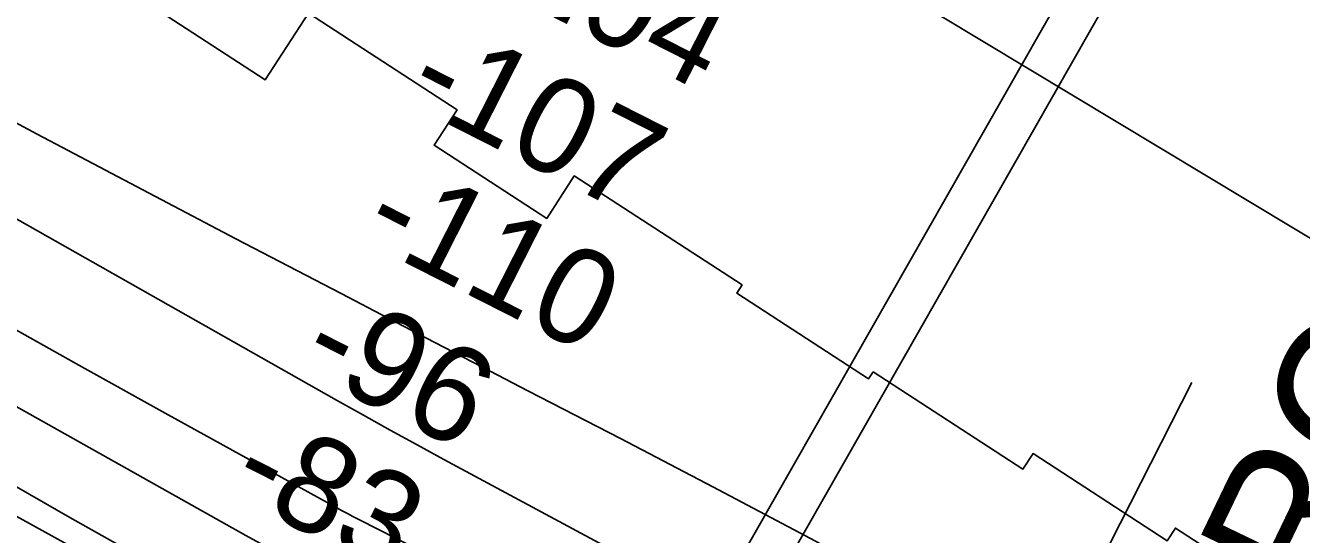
# Model space of a CAD drawing. Extents: x 3823584 to 3861785, y 301729 to 327625.
# Drawn here: x 3842355 to 3843247, y 321461 to 321817 of the extents above; entities that cross this region are included whole.
import ezdxf

# ---------------------------------------------------------------- set-up
doc = ezdxf.new("R2010")
doc.units = 0
for name, color, linetype in [('V-CHAN-NAID', 7, 'Continuous'), ('V-RIVR-EDGE', 7, 'Continuous'), ('V-RIVR-RANG', 7, 'Continuous'), ('V-RRAP-RVMT', 7, 'Continuous'), ('V-TOPO-MAJR', 7, 'Continuous'), ('V-TOPO-MINR', 7, 'Continuous'), ('V-UTIL-LINE', 7, 'Continuous')]:
    doc.layers.add(name, color=color, linetype=linetype)

msp = doc.modelspace()

# ---------------------------------------------------------------- linework, layer by layer
at = {"layer": 'V-RIVR-EDGE'}
msp.add_spline([(3836304.38, 325474.18), (3836346.41, 325438.32), (3836389.41, 325406.07), (3836417.64, 325385.43), (3836442.67, 325366.73), (3836470.25, 325340.95), (3836497.82, 325313.88), (3836554.9, 325258.45), (3836598.51, 325215.91), (3836636.36, 325181.1), (3836681.26, 325139.85), (3836737.07, 325093.42), (3836790.94, 325041.22), (3836840.33, 324993.52), (3836889.07, 324947.12), (3836934.61, 324907.14), (3836980.81, 324871.03), (3837015.47, 324849.09), (3837040.49, 324829.1), (3837085.39, 324787.2), (3837143.76, 324734.34), (3837181.61, 324700.82), (3837223.29, 324659.57), (3837272.05, 324619.59), (3837314.38, 324579.63), (3837346.45, 324546.76), (3837364.4, 324527.43), (3837395.83, 324500.35), (3837442.02, 324462.31), (3837492.71, 324422.97), (3837554.31, 324372.67), (3837573.56, 324361.05), (3837583.2, 324359.1), (3837596.69, 324352.64), (3837621.08, 324337.79), (3837648.03, 324319.73), (3837677.54, 324292.01), (3837718.58, 324249.48), (3837753.85, 324214.68), (3837781.43, 324188.89), (3837800.05, 324179.85), (3837819.95, 324170.8), (3837850.72, 324134.08), (3837874.45, 324110.23), (3837909.07, 324073.5), (3837941.78, 324040.64), (3837989.87, 323991.66), (3838022.58, 323960.72), (3838034.12, 323947.83), (3838046.3, 323933.66), (3838066.83, 323916.25), (3838089.91, 323892.41), (3838140.59, 323849.21), (3838186.14, 323811.17), (3838215.65, 323785.38), (3838265.68, 323736.4), (3838297.1, 323707.39), (3838336.87, 323671.94), (3838359.95, 323645.52), (3838385.62, 323627.46), (3838404.24, 323615.84), (3838421.56, 323601.65), (3838441.44, 323582.32), (3838460.05, 323567.49), (3838468.4, 323563.61), (3838484.45, 323555.21), (3838548.59, 323496.55), (3838595.44, 323464.29), (3838649.98, 323422.37), (3838701.3, 323379.82), (3838749.43, 323345.62), (3838798.22, 323317.86), (3838856.62, 323274.64), (3838932.99, 323221.74), (3838989.47, 323184.31), (3839037.6, 323150.12), (3839068.42, 323134.62), (3839093.42, 323104.98), (3839110.73, 323086.94), (3839122.93, 323081.12), (3839143.46, 323065.64), (3839172.34, 323044.36), (3839190.96, 323032.74), (3839215.99, 323015.96), (3839242.32, 323006.26), (3839316.8, 322969.43), (3839341.84, 322955.87), (3839371.38, 322944.22), (3839391.29, 322935.81), (3839417.61, 322920.32), (3839461.26, 322894.5), (3839483.71, 322873.23), (3839520.3, 322851.28), (3839555.6, 322828.69), (3839599.9, 322806.72), (3839718.7, 322751.14), (3839768.14, 322726.59), (3839807.95, 322705.92), (3839836.85, 322696.21), (3839865.1, 322680.71), (3839887.57, 322667.8), (3839924.17, 322652.28), (3839969.76, 322630.31), (3840004.43, 322612.22), (3840037.82, 322597.35), (3840085.35, 322579.88), (3840108.46, 322565.68), (3840121.92, 322548.93), (3840123.18, 322539.92), (3840122.53, 322533.5), (3840118, 322521.29), (3840112.84, 322514.24), (3840095.47, 322509.14), (3840089.68, 322509.15), (3840085.17, 322504.66), (3840084.51, 322498.23), (3840085.78, 322491.8), (3840130.72, 322467.26), (3840169.89, 322448.52), (3840197.51, 322439.45), (3840209.08, 322437.5), (3840231.59, 322441.3), (3840246.39, 322448.98), (3840266.34, 322458.57), (3840273.43, 322466.27), (3840278.59, 322471.4), (3840288.9, 322480.37), (3840295.98, 322484.85), (3840301.77, 322484.84), (3840308.2, 322484.82), (3840320.4, 322479.01), (3840324.87, 322470), (3840326.78, 322461.63), (3840338.32, 322450.03), (3840344.74, 322444.88), (3840366.58, 322437.75), (3840385.84, 322428.06), (3840421.8, 322409.33), (3840466.1, 322385.43), (3840492.41, 322368.65), (3840506.53, 322357.04), (3840533.49, 322340.26), (3840559.18, 322331.2), (3840587.44, 322322.13), (3840611.85, 322311.78), (3840642.02, 322296.28), (3840678.62, 322276.26), (3840712.64, 322255.6), (3840733.18, 322242.05), (3840784.53, 322210.43), (3840835.89, 322183.3), (3840892.39, 322153.59), (3840923.85, 322139.37), (3840950.82, 322127.08), (3840989.33, 322099.99), (3841017.57, 322082.56), (3841061.24, 322062.52), (3841092.69, 322044.45), (3841151.1, 322005.09), (3841210.78, 321964.44), (3841240.29, 321939.29), (3841299.97, 321894.79), (3841335.89, 321862.55), (3841374.37, 321823.89), (3841411.57, 321789.72), (3841444.92, 321758.14), (3841469.94, 321736.22), (3841482.12, 321723.98), (3841496.22, 321704.66), (3841509.05, 321694.34), (3841523.18, 321687.23), (3841573.9, 321660.75), (3841623.97, 321631.69), (3841667.62, 321606.51), (3841696.52, 321593.59), (3841738.26, 321575.48), (3841787.07, 321556.72), (3841815.99, 321552.15), (3841851.33, 321544.99), (3841886.66, 321533.33), (3841930.32, 321511.36), (3841950.22, 321498.46), (3841977.18, 321482.96), (3841998.38, 321476.48), (3842052.99, 321463.49), (3842082.55, 321456.34), (3842109.52, 321444.7), (3842146.12, 321427.26), (3842196.2, 321402.06), (3842241.13, 321374.95), (3842288.63, 321345.26), (3842321.38, 321327.18), (3842366.94, 321295.56), (3842395.19, 321280.07), (3842429.22, 321264.55), (3842452.35, 321258.71), (3842470.97, 321249.66)], degree=3, dxfattribs=at)
at = {"layer": 'V-RIVR-RANG'}
msp.add_line((3842832.27, 320901.73), (3843170.83, 321567.61), dxfattribs=at)
at = {"layer": 'V-RRAP-RVMT'}
for points in [[(3841932.93, 321972.08), (3841950.98, 321962.27), (3842018.81, 322075.16), (3842117.46, 322015.88), (3842118.08, 322016.99), (3842215.23, 321963.13), (3842229.38, 321986.73), (3842349.39, 321914.63), (3842343.06, 321904.09), (3842450.21, 321839.71), (3842444.3, 321829.87), (3842522.32, 321779.23), (3842552.53, 321825.75), (3842656.53, 321758.21), (3842640.44, 321733.44), (3842719.28, 321682.24), (3842738.58, 321711.98), (3842856, 321635.73), (3842852.32, 321630.07), (3842944.58, 321570.16), (3842947.71, 321574.98)], [(3842947.71, 321574.98), (3843052.57, 321506.95), (3843059.59, 321517.75), (3843153.51, 321456.77), (3843159.28, 321465.65), (3843250.69, 321406.29)]]:
    msp.add_lwpolyline(points, dxfattribs=at)
at = {"layer": 'V-TOPO-MAJR'}
for points in [[(3844485.02, 321092.53), (3844139.12, 321232.48), (3844060.22, 321264.73), (3843981.47, 321297.36), (3843902.96, 321330.56), (3843824.61, 321364.13), (3843700.79, 321417.7), (3843684.58, 321425), (3843668.52, 321432.61), (3843652.69, 321440.68), (3843637.01, 321449.07), (3843535.48, 321505.29), (3843469.35, 321542.37), (3843403.49, 321579.92), (3843338.05, 321618.19), (3843272.87, 321656.92), (3842932.73, 321861.56)], [(3842293.52, 321778.21), (3842362.77, 321741.23), (3842432.2, 321704.56), (3842501.74, 321668.1), (3842575.45, 321629.67), (3842608.22, 321612.6), (3842641.01, 321595.55), (3842673.8, 321578.53), (3842706.61, 321561.52), (3842770.81, 321528.27), (3842835.61, 321494.44), (3842900.27, 321460.34), (3842964.71, 321425.82), (3843029, 321391.03), (3843450.92, 321160.93)], [(3842060.11, 321632.8), (3842508.85, 321385.18), (3842518.5, 321379.89), (3842528.19, 321374.66), (3842537.91, 321369.49), (3842547.65, 321364.37), (3843222.59, 321012.83), (3843255.01, 320996.09), (3843287.51, 320979.51), (3843320.12, 320963.16), (3843352.82, 320946.97), (3843409.53, 320919.13), (3843413.94, 320916.98), (3843418.35, 320914.86), (3843422.78, 320912.76), (3843427.21, 320910.68), (3843476.14, 320887.94), (3843505.06, 320874.53), (3843533.99, 320861.15), (3843562.94, 320847.81), (3843591.9, 320834.49), (3844242.57, 320535.89), (3844274.07, 320521.39), (3844305.54, 320506.83)]]:
    msp.add_lwpolyline(points, dxfattribs=at)
at = {"layer": 'V-TOPO-MINR'}
for points in [[(3841734.91, 322029.09), (3842572.26, 321555.18), (3842590.96, 321544.67), (3842609.71, 321534.25), (3842628.52, 321523.94), (3842647.38, 321513.71), (3842888.96, 321383.69), (3842988.99, 321330.44), (3843089.33, 321277.78), (3843190.15, 321226.04), (3843291.28, 321174.9), (3843463.64, 321088.72), (3843478.84, 321081.15), (3843494.07, 321073.63), (3843509.32, 321066.16), (3843524.59, 321058.73), (3843804.65, 320923.16), (3843898.96, 320877.48), (3843993.25, 320831.76), (3844087.51, 320785.99), (3844181.76, 320740.19), (3844347.77, 320659.47)], [(3841947.48, 321775.4), (3842508.83, 321460.58), (3842533.48, 321446.93), (3842558.23, 321433.45), (3842583.12, 321420.25), (3842608.12, 321407.23), (3842789.82, 321313.81), (3842899.36, 321257.98), (3843009.17, 321202.67), (3843119.37, 321148.15), (3843229.83, 321094.15), (3843423.61, 321000.27), (3843437.38, 320993.61), (3843451.15, 320986.97), (3843464.94, 320980.34), (3843478.73, 320973.73), (3843661.02, 320886.53), (3843765.98, 320836.35), (3843870.95, 320786.2), (3843975.94, 320736.11), (3844080.95, 320686.05), (3844273.4, 320594.35), (3844303.01, 320580.26)], [(3842329.37, 321614.55), (3842391.81, 321579.54), (3842454.4, 321544.81), (3842572.52, 321479.79), (3842576.19, 321477.8), (3842579.87, 321475.83), (3842583.56, 321473.89), (3842587.27, 321471.98), (3842780.45, 321373.72), (3842880.88, 321322.92), (3842981.45, 321272.42), (3843082.24, 321222.37), (3843183.19, 321172.62), (3843398.65, 321067.03)], [(3842348.23, 321494.57), (3842385.51, 321473.16), (3842422.97, 321452.07), (3842460.54, 321431.18), (3842531.52, 321392.12), (3842533.71, 321390.93), (3842538.09, 321388.59), (3842540.3, 321387.45), (3842695.72, 321307.5), (3842775.77, 321266.63), (3842855.98, 321226.09), (3842936.43, 321186.04), (3843017.05, 321146.31), (3843361.4, 320977.91), (3843396.53, 320960.82), (3843431.7, 320943.82), (3843466.94, 320926.96), (3843502.23, 320910.2), (3843918.75, 320713.36), (3843984.74, 320682.27), (3844050.77, 320651.3), (3844116.88, 320620.48), (3844183.05, 320589.77), (3844309.14, 320531.44)]]:
    msp.add_lwpolyline(points, dxfattribs=at)
at = {"layer": 'V-UTIL-LINE'}
for p, q in [((3842674.54, 321128.47), (3844309.41, 323994.94)), ((3842696.34, 321106.67), (3844331.21, 323973.14))]:
    msp.add_line(p, q, dxfattribs=at)

# ---------------------------------------------------------------- texts
at = {"layer": 'V-CHAN-NAID'}
for s, rotation, p in [('ALBERTA "27" (27.8)', 61.41951, (3842160.09, 321577.8)), ('CHEVRON SUNRISE', 64.30503, (3843101.57, 321073.12)), ('BOAT LANDING (27.5)', 64.30503, (3843217.55, 321015.35))]:
    msp.add_text(s, height=100, rotation=rotation, dxfattribs=at).set_placement(p)
at = {"layer": 'V-RIVR-RANG'}
for s, p in [('-104', (3842666.2, 321852.3)), ('-107', (3842618.13, 321764.56)), ('-110', (3842587.46, 321667.98)), ('-96', (3842544.09, 321577.85)), ('-83', (3842494.84, 321490.71))]:
    msp.add_text(s, height=67, rotation=333.08522, dxfattribs=at).set_placement(p)

doc.saveas('drawing.dxf')
